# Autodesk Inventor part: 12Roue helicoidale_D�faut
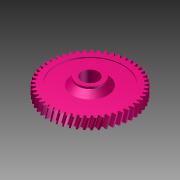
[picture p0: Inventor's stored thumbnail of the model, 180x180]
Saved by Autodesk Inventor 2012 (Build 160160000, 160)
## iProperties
Created: 2011-01
Part Number: 12Roue helicoidale_D�faut
Document SubType Name: Modeling
Designer: eric
Density: 1 g/cm^3
Mass: 54.2193 g
Surface Area: 182.103 cm^2
Volume: 54.2193 cm^3
Material: Par défaut
Author: eric
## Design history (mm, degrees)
feature "Base1"
sketch "Esquisse1"
  geometry: C1 r 34 at (0, 0) reference; C2 r 40 at (0, 0)
  constraints: 1 centre point, 1 coincident
  dimensions: "d0" = 80 diameter of C2
feature "SrfExtrusion1" sketch "Esquisse1" dims "d1" = 10, "d2" = 0
node "Corps solides"
node "Corps surfaciques"
body "Srf1"
node "Solide1"
